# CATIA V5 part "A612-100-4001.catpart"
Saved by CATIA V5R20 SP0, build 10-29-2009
Part number: A612-100-4001
Source: Unknown
Property "A": "30.000"
Property "ARTICLENO": "A612-100-4001"
Property "B": "40.000"
Property "BOMINFO": "A612-100-4001"
Property "CODE": "A612-100-4001"
Property "D": "22.000"
Property "FORM": "C"
Property "L": "400.000"
Property "L1": "45.000"
Property "L2": "80.000"
Property "L3": "75.000"
Property "LINA": "A612-100-4001"
Property "NB": "A612-100-4001"
Property "NBSYN": "$CODE."
Property "NN": "A612"
Property "NT": "CDI 3357 E-Type Wear Plates, steel and self-lubricating"
Property "SUPPLIER": "CF"
Property "T": "30.000"
Property "W": "100.000"
Bounding box of the stored display mesh (mm): x 0 to 30, y 0 to 400, z 0 to 100
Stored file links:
  C:\Users\Utente\Desktop\3D files A612\A612-100-4001.catpart
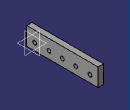
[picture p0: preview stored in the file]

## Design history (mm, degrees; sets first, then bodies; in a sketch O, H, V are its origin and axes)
Body1 "Geometry.1" (main body)
  Solid1 "A612-100-4001.catpart": solid without history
